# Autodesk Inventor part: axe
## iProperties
Shininess: 20.0
Length Units: 11269
Angle Units: 11279
Time Units: 11290
Mass Units: 11283
Length Display Precision: 3
Angle Display Precision: 2
Compacted: True
Created: 2003-02
Part Number: axe
Material: Par défaut
Document SubType Name: Modélisation
Designer: robert
Density: 1 g/cm^3
Density: 0.0
Volumn: 0.0
Area: 0.0
PropertySet Name: Model Information
Control State: 0
Master: False
Checked Out: False
Author: robert
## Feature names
1. Révolution1 [Revolution]
